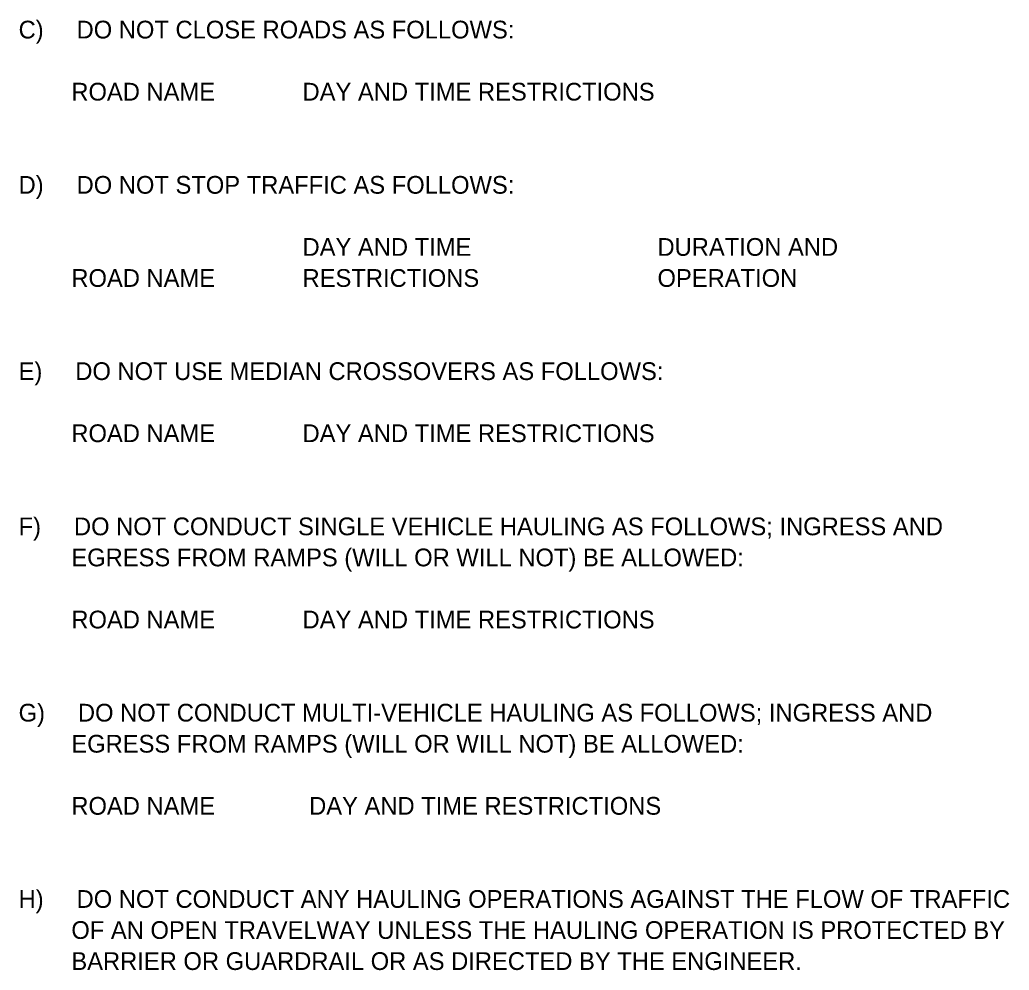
# Model space of a CAD drawing. Extents: x 2485109 to 2490507, y 368607 to 371384.
# Drawn here: x 2485108.9 to 2485499.1, y 369784.7 to 370159.7 of the extents above; entities that cross this region are included whole.
import ezdxf

# ---------------------------------------------------------------- set-up
doc = ezdxf.new("R2010")
doc.units = 0
doc.layers.add('TC SHEET TEXT', color=7, linetype='Continuous')

msp = doc.modelspace()

# ---------------------------------------------------------------- texts
at = {"layer": 'TC SHEET TEXT'}
for s, p in [('C)     DO NOT CLOSE ROADS AS FOLLOWS:', (2485108.41, 370152.33)), ('        ROAD NAME ', (2485108.41, 370127.83)), ('DAY AND TIME RESTRICTIONS', (2485220.41, 370127.83)), ('D)     DO NOT STOP TRAFFIC AS FOLLOWS:', (2485108.41, 370091.08)), ('DAY AND TIME', (2485220.41, 370066.58)), ('DURATION AND', (2485360.41, 370066.58)), ('        ROAD NAME ', (2485108.41, 370054.33)), ('RESTRICTIONS ', (2485220.41, 370054.33)), ('OPERATION', (2485360.41, 370054.33)), ('E)     DO NOT USE MEDIAN CROSSOVERS AS FOLLOWS:', (2485108.41, 370017.58)), ('        ROAD NAME ', (2485108.41, 369993.08)), ('DAY AND TIME RESTRICTIONS', (2485220.41, 369993.08)), ('F)     DO NOT CONDUCT SINGLE VEHICLE HAULING AS FOLLOWS; INGRESS AND', (2485108.41, 369956.33)), ('        EGRESS FROM RAMPS (WILL OR WILL NOT) BE ALLOWED:', (2485108.41, 369944.08)), ('        ROAD NAME ', (2485108.41, 369919.58)), ('DAY AND TIME RESTRICTIONS', (2485220.41, 369919.58)), ('G)     DO NOT CONDUCT MULTI-VEHICLE HAULING AS FOLLOWS; INGRESS AND', (2485108.41, 369882.83)), ('        EGRESS FROM RAMPS (WILL OR WILL NOT) BE ALLOWED:', (2485108.41, 369870.58)), ('        ROAD NAME', (2485108.41, 369846.08)), (' DAY AND TIME RESTRICTIONS', (2485220.41, 369846.08)), ('H)     DO NOT CONDUCT ANY HAULING OPERATIONS AGAINST THE FLOW OF TRAFFIC', (2485108.41, 369809.33)), ('        OF AN OPEN TRAVELWAY UNLESS THE HAULING OPERATION IS PROTECTED BY', (2485108.41, 369797.08)), ('        BARRIER OR GUARDRAIL OR AS DIRECTED BY THE ENGINEER.', (2485108.41, 369784.83))]:
    msp.add_text(s, height=7, dxfattribs=at).set_placement(p)

doc.saveas('drawing.dxf')
